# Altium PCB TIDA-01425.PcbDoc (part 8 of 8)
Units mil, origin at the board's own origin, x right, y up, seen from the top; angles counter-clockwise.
Board outline 7000 x 3600 mil, 6 copper layers (Layer 1 - Top Layer, Layer 2 - GND, Layer 3 - Signal / PWR, Layer 4 - Signal / PWR, Layer 5 - PWR, Layer 6 - Bottom Layer), stack 60.4 mil thick; 495 components, 307 nets, 2058 pads, 1870 vias.
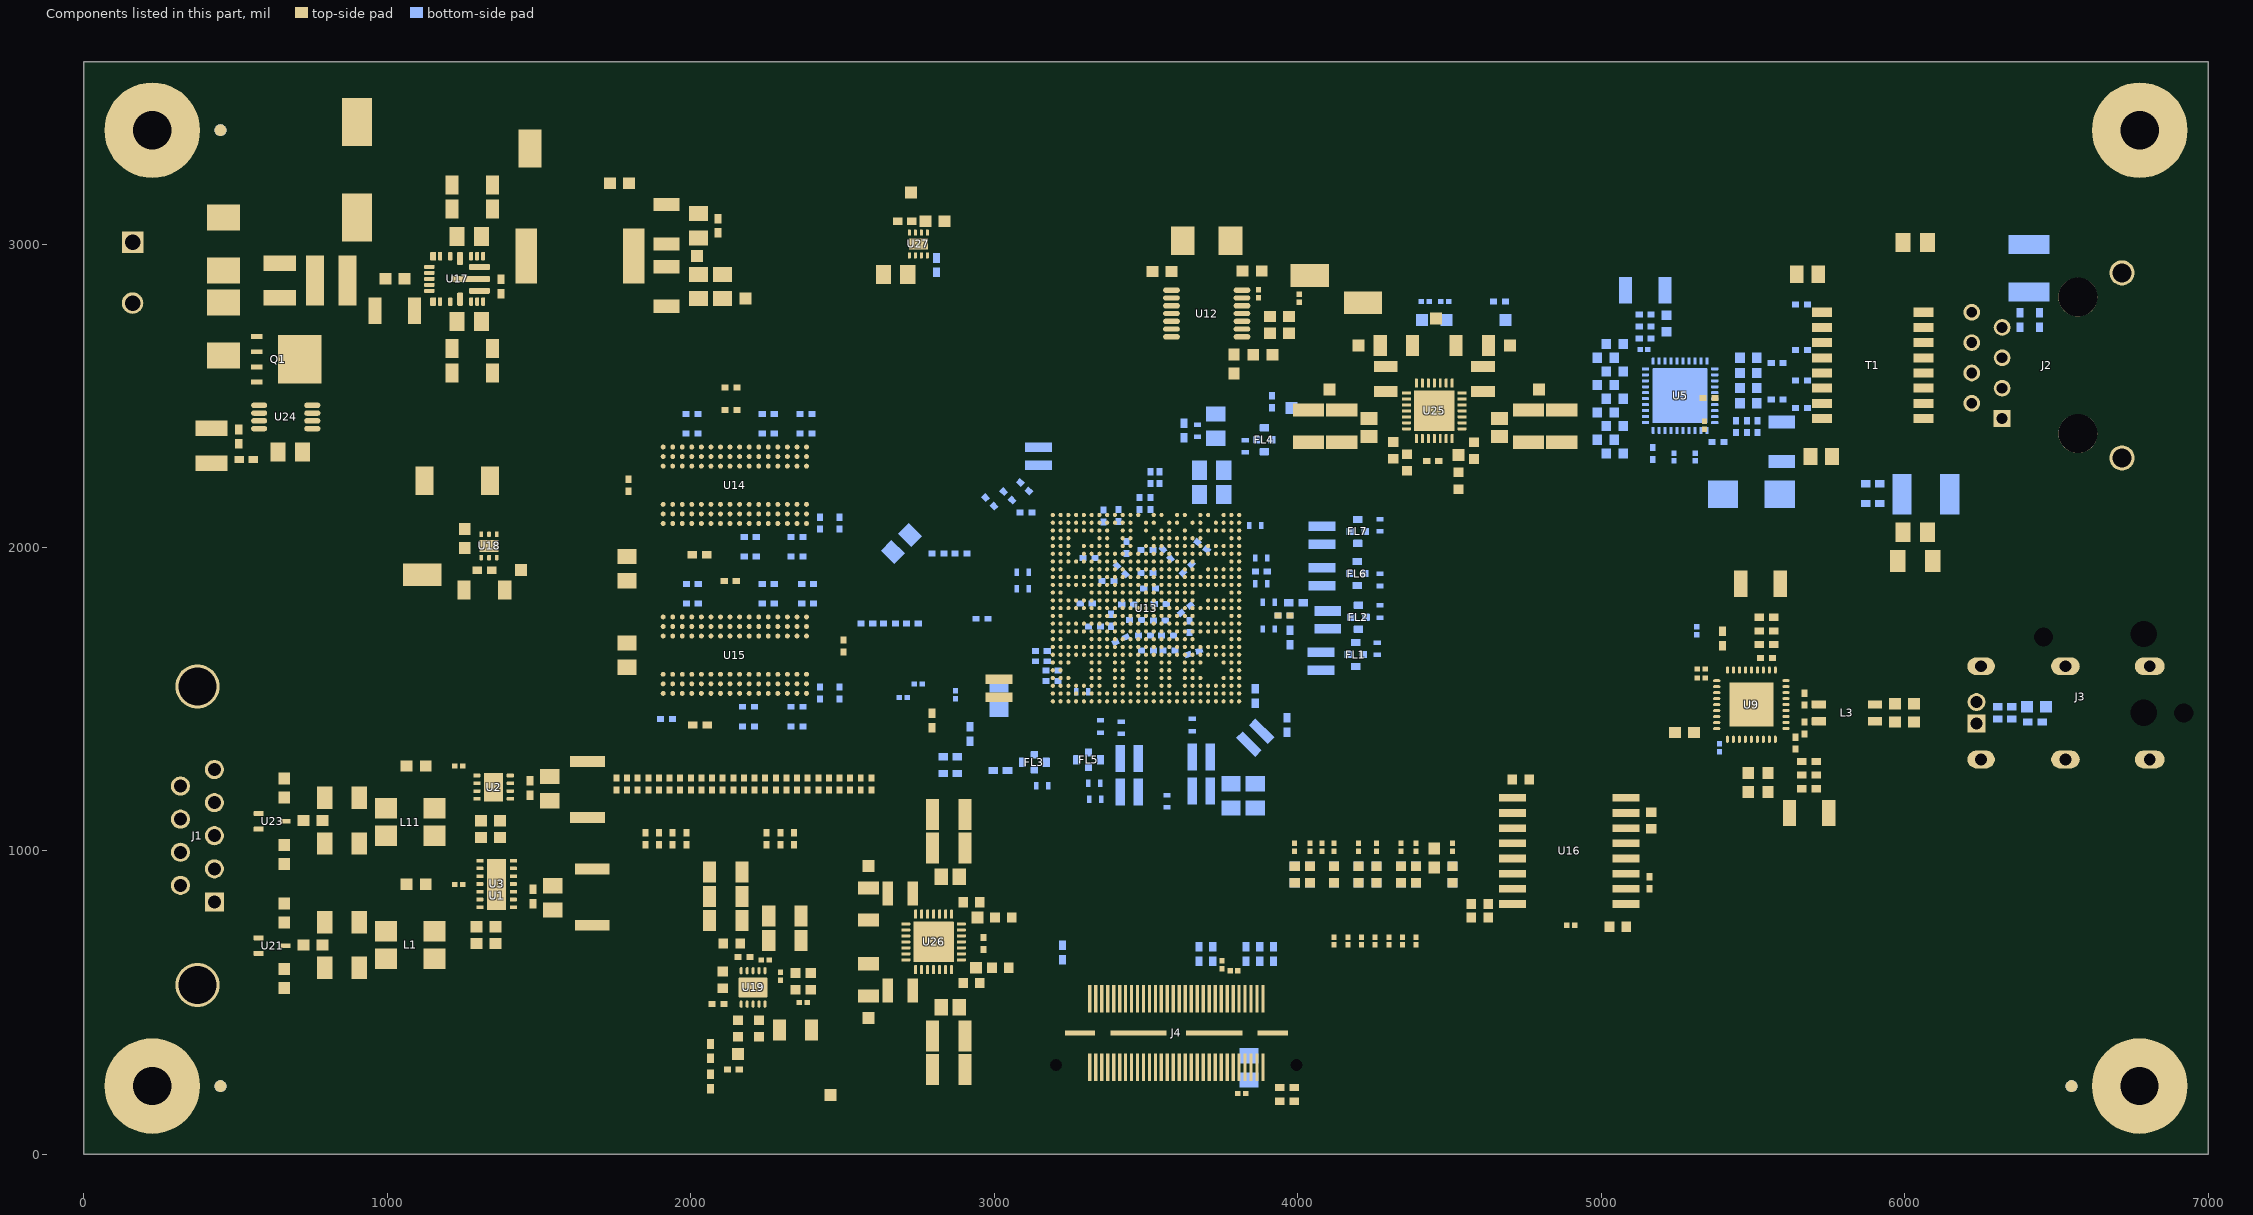
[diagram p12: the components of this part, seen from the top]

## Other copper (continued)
Layer 3 - Signal / PWR:
  pour cut-out: 6095,2325 5695,2325 5695,2875 6095,2875
  pour cut-out: 2655,1242.42 2655,1420 2986,1751 3258,1751 3332,1825 3332,2097 3500,2265 3500,2380 3260,2620 1884,2620 1771,2507 1771,1660 1697,1586 1697,1292 1697,1243.03
  pour cut-out: 3401.28,1813 3400.27,1818.08 3397.39,1822.38 3393.08,1825.26 3388,1826.27 3382.92,1825.26 3378.62,1822.38 3375.74,1818.08 3374.73,1813 3375.74,1807.92 3378.62,1803.61 3382.92,1800.73 3388,1799.72 3393.08,1800.73 3397.39,1803.61 3400.27,1807.92 3401.28,1813
  pour cut-out: 3446.28,1787.5 3445.27,1792.58 3442.39,1796.88 3438.08,1799.76 3433,1800.77 3427.92,1799.76 3423.62,1796.88 3420.74,1792.58 3419.73,1787.5 3420.74,1782.42 3423.62,1778.11 3427.92,1775.23 3433,1774.22 3438.08,1775.23 3442.39,1778.11 3445.27,1782.42 3446.28,1787.5
  pour cut-out: 3497.28,1787.5 3496.27,1792.58 3493.39,1796.88 3489.08,1799.76 3484,1800.77 3478.92,1799.76 3474.62,1796.88 3471.74,1792.58 3470.73,1787.5 3471.74,1782.42 3474.62,1778.11 3478.92,1775.23 3484,1774.22 3489.08,1775.23 3493.39,1778.11 3496.27,1782.42 3497.28,1787.5
  pour cut-out: 3497.53,1889.65 3496.52,1894.73 3493.64,1899.03 3489.33,1901.91 3484.25,1902.92 3479.17,1901.91 3474.87,1899.03 3471.99,1894.73 3470.98,1889.65 3471.99,1884.57 3474.87,1880.26 3479.17,1877.38 3484.25,1876.37 3489.33,1877.38 3493.64,1880.26 3496.52,1884.57 3497.53,1889.65
  pour cut-out: 3446.08,1889.6 3445.07,1894.68 3442.19,1898.98 3437.88,1901.86 3432.8,1902.87 3427.72,1901.86 3423.42,1898.98 3420.54,1894.68 3419.53,1889.6 3420.54,1884.52 3423.42,1880.21 3427.72,1877.33 3432.8,1876.32 3437.88,1877.33 3442.19,1880.21 3445.07,1884.52 3446.08,1889.6
  pour cut-out: 3471.38,1838.5 3470.37,1843.58 3467.49,1847.88 3463.18,1850.76 3458.1,1851.77 3453.02,1850.76 3448.72,1847.88 3445.84,1843.58 3444.83,1838.5 3445.84,1833.42 3448.72,1829.11 3453.02,1826.23 3458.1,1825.22 3463.18,1826.23 3467.49,1829.11 3470.37,1833.42 3471.38,1838.5
  pour cut-out: 3522.78,1838.5 3521.77,1843.58 3518.89,1847.88 3514.58,1850.76 3509.5,1851.77 3504.42,1850.76 3500.12,1847.88 3497.24,1843.58 3496.23,1838.5 3497.24,1833.42 3500.12,1829.11 3504.42,1826.23 3509.5,1825.22 3514.58,1826.23 3518.89,1829.11 3521.77,1833.42 3522.78,1838.5
  pour cut-out: 3548.68,1787 3547.67,1792.08 3544.79,1796.38 3540.48,1799.26 3535.4,1800.27 3530.32,1799.26 3526.02,1796.38 3523.14,1792.08 3522.13,1787 3523.14,1781.92 3526.02,1777.61 3530.32,1774.73 3535.4,1773.72 3540.48,1774.73 3544.79,1777.61 3547.67,1781.92 3548.68,1787
  pour cut-out: 3548.78,1889.4 3547.77,1894.48 3544.89,1898.78 3540.58,1901.66 3535.5,1902.67 3530.42,1901.66 3526.12,1898.78 3523.24,1894.48 3522.23,1889.4 3523.24,1884.32 3526.12,1880.01 3530.42,1877.13 3535.5,1876.12 3540.58,1877.13 3544.89,1880.01 3547.77,1884.32 3548.78,1889.4
  pour cut-out: 3573.78,1838.5 3572.77,1843.58 3569.89,1847.88 3565.58,1850.76 3560.5,1851.77 3555.42,1850.76 3551.12,1847.88 3548.24,1843.58 3547.23,1838.5 3548.24,1833.42 3551.12,1829.11 3555.42,1826.23 3560.5,1825.22 3565.58,1826.23 3569.89,1829.11 3572.77,1833.42 3573.78,1838.5
  pour cut-out: 2989.3,1463 2988.21,1468.47 2985.11,1473.1 2980.47,1476.2 2975,1477.29 2969.53,1476.2 2964.9,1473.1 2961.8,1468.47 2960.71,1463 2961.8,1457.53 2964.9,1452.89 2969.53,1449.79 2975,1448.7 2980.47,1449.79 2985.11,1452.89 2988.21,1457.53 2989.3,1463
  pour cut-out: 2936.3,1453.51 2935.21,1458.98 2932.11,1463.61 2927.47,1466.71 2922,1467.8 2916.53,1466.71 2911.9,1463.61 2908.8,1458.98 2907.71,1453.51 2908.8,1448.04 2911.9,1443.4 2916.53,1440.3 2922,1439.21 2927.47,1440.3 2932.11,1443.4 2935.21,1448.04 2936.3,1453.51
  pour cut-out: 3073.9,1463 3072.81,1468.47 3069.71,1473.1 3065.07,1476.2 3059.6,1477.29 3054.13,1476.2 3049.5,1473.1 3046.4,1468.47 3045.31,1463 3046.4,1457.53 3049.5,1452.89 3054.13,1449.79 3059.6,1448.7 3065.07,1449.79 3069.71,1452.89 3072.81,1457.53 3073.9,1463
  pour cut-out: 3206.87,1471.22 3205.86,1476.3 3202.98,1480.6 3198.67,1483.48 3193.59,1484.49 3188.51,1483.48 3184.21,1480.6 3181.33,1476.3 3180.32,1471.22 3181.33,1466.14 3184.21,1461.83 3188.51,1458.95 3193.59,1457.94 3198.67,1458.95 3202.98,1461.83 3205.86,1466.14 3206.87,1471.22
  pour cut-out: 3650.78,2017.5 3649.77,2022.58 3646.89,2026.88 3642.58,2029.76 3637.5,2030.77 3632.42,2029.76 3628.12,2026.88 3625.24,2022.58 3624.23,2017.5 3625.24,2012.42 3628.12,2008.11 3632.42,2005.23 3637.5,2004.22 3642.58,2005.23 3646.89,2008.11 3649.77,2012.42 3650.78,2017.5
  pour cut-out: 3116.34,1655.01 3115.25,1660.48 3112.15,1665.11 3107.51,1668.21 3102.04,1669.3 3096.57,1668.21 3091.94,1665.11 3088.84,1660.48 3087.75,1655.01 3088.84,1649.54 3091.94,1644.9 3096.57,1641.8 3102.04,1640.71 3107.51,1641.8 3112.15,1644.9 3115.25,1649.54 3116.34,1655.01
  pour cut-out: 3343.78,1787.1 3342.77,1792.18 3339.89,1796.48 3335.58,1799.36 3330.5,1800.37 3325.42,1799.36 3321.12,1796.48 3318.24,1792.18 3317.23,1787.1 3318.24,1782.02 3321.12,1777.71 3325.42,1774.83 3330.5,1773.82 3335.58,1774.83 3339.89,1777.71 3342.77,1782.02 3343.78,1787.1
  pour cut-out: 3446.38,1659.1 3445.37,1664.18 3442.49,1668.48 3438.18,1671.36 3433.1,1672.37 3428.02,1671.36 3423.72,1668.48 3420.84,1664.18 3419.83,1659.1 3420.84,1654.02 3423.72,1649.71 3428.02,1646.83 3433.1,1645.82 3438.18,1646.83 3442.49,1649.71 3445.37,1654.02 3446.38,1659.1
  pour cut-out: 3462.1,2124.04 3461.09,2129.12 3458.21,2133.42 3453.9,2136.3 3448.82,2137.31 3443.74,2136.3 3439.44,2133.42 3436.56,2129.12 3435.55,2124.04 3436.56,2118.96 3439.44,2114.65 3443.74,2111.77 3448.82,2110.76 3453.9,2111.77 3458.21,2114.65 3461.09,2118.96 3462.1,2124.04
  pour cut-out: 5695,2398.81 5671.19,2398.81 5655,2415 5655,2445 5650,2450 5630,2450 5607,2473 5595,2473 5588,2466 5500,2466 5482,2484 5392,2484 5301,2575 5301,2686 5368,2753 5648,2753 5654,2759 5654,2788 5665,2799 5695,2799
  text ".Layer_Name" at 577,-858.49 h60
Layer 4 - Signal / PWR:
  pour cut-out: 6095,2325 5695,2325 5695,2875 6095,2875
  pour cut-out: 3936.99,1913.21 3935.91,1918.68 3932.81,1923.32 3928.17,1926.42 3922.7,1927.5 3917.23,1926.42 3912.59,1923.32 3909.49,1918.68 3908.41,1913.21 3909.49,1907.74 3912.59,1903.1 3917.23,1900 3922.7,1898.92 3928.17,1900 3932.81,1903.1 3935.91,1907.74 3936.99,1913.21
  pour cut-out: 2655,1242.41 2655,1420 2986,1751 3258,1751 3346,1839 3346,1997 3456.24,2107.24 3456.24,2141.93 3500,2185.7 3500,2380 3260,2620 1884,2620 1771,2507 1771,1660 1697,1586 1697,1292 1697,1243.01
  pour cut-out: 4261.3,2053 4260.21,2058.47 4257.11,2063.1 4252.47,2066.2 4247,2067.29 4241.53,2066.2 4236.9,2063.1 4233.8,2058.47 4232.71,2053 4233.8,2047.53 4236.9,2042.89 4241.53,2039.79 4247,2038.7 4252.47,2039.79 4257.11,2042.89 4260.21,2047.53 4261.3,2053
  pour cut-out: 4154.3,2053 4153.21,2058.47 4150.11,2063.1 4145.47,2066.2 4140,2067.29 4134.53,2066.2 4129.9,2063.1 4126.8,2058.47 4125.71,2053 4126.8,2047.53 4129.9,2042.89 4134.53,2039.79 4140,2038.7 4145.47,2039.79 4150.11,2042.89 4153.21,2047.53 4154.3,2053
  pour cut-out: 4151.4,2018.1 4150.31,2023.57 4147.21,2028.2 4142.57,2031.3 4137.1,2032.39 4131.63,2031.3 4127,2028.2 4123.9,2023.57 4122.81,2018.1 4123.9,2012.63 4127,2007.99 4131.63,2004.89 4137.1,2003.8 4142.57,2004.89 4147.21,2007.99 4150.31,2012.63 4151.4,2018.1
  pour cut-out: 4079.3,2380 4078.21,2385.47 4075.11,2390.1 4070.47,2393.2 4065,2394.29 4059.53,2393.2 4054.9,2390.1 4051.8,2385.47 4050.71,2380 4051.8,2374.53 4054.9,2369.89 4059.53,2366.79 4065,2365.7 4070.47,2366.79 4075.11,2369.89 4078.21,2374.53 4079.3,2380
  pour cut-out: 4050.8,2053.1 4049.71,2058.57 4046.61,2063.2 4041.97,2066.3 4036.5,2067.39 4031.03,2066.3 4026.4,2063.2 4023.3,2058.57 4022.21,2053.1 4023.3,2047.63 4026.4,2042.99 4031.03,2039.89 4036.5,2038.8 4041.97,2039.89 4046.61,2042.99 4049.71,2047.63 4050.8,2053.1
  pour cut-out: 4050.9,2018.1 4049.81,2023.57 4046.71,2028.2 4042.07,2031.3 4036.6,2032.39 4031.13,2031.3 4026.5,2028.2 4023.4,2023.57 4022.31,2018.1 4023.4,2012.63 4026.5,2007.99 4031.13,2004.89 4036.6,2003.8 4042.07,2004.89 4046.71,2007.99 4049.81,2012.63 4050.9,2018.1
  pour cut-out: 3972.3,2355 3971.21,2360.47 3968.11,2365.1 3963.47,2368.2 3958,2369.29 3952.53,2368.2 3947.9,2365.1 3944.8,2360.47 3943.71,2355 3944.8,2349.53 3947.9,2344.89 3952.53,2341.79 3958,2340.7 3963.47,2341.79 3968.11,2344.89 3971.21,2349.53 3972.3,2355
  pour cut-out: 3943.3,1390 3942.21,1395.47 3939.11,1400.1 3934.47,1403.2 3929,1404.29 3923.53,1403.2 3918.9,1400.1 3915.8,1395.47 3914.71,1390 3915.8,1384.53 3918.9,1379.89 3923.53,1376.79 3929,1375.7 3934.47,1376.79 3939.11,1379.89 3942.21,1384.53 3943.3,1390
  pour cut-out: 3918.6,2072.8 3917.51,2078.27 3914.41,2082.9 3909.77,2086 3904.3,2087.09 3898.83,2086 3894.2,2082.9 3891.1,2078.27 3890.01,2072.8 3891.1,2067.33 3894.2,2062.69 3898.83,2059.59 3904.3,2058.5 3909.77,2059.59 3914.41,2062.69 3917.51,2067.33 3918.6,2072.8
  pour cut-out: 3850.5,1430.2 3849.41,1435.67 3846.31,1440.3 3841.67,1443.4 3836.2,1444.49 3830.73,1443.4 3826.1,1440.3 3823,1435.67 3821.91,1430.2 3823,1424.73 3826.1,1420.09 3830.73,1416.99 3836.2,1415.9 3841.67,1416.99 3846.31,1420.09 3849.41,1424.73 3850.5,1430.2
  pour cut-out: 3876.2,1455.3 3875.11,1460.77 3872.01,1465.4 3867.37,1468.5 3861.9,1469.59 3856.43,1468.5 3851.8,1465.4 3848.7,1460.77 3847.61,1455.3 3848.7,1449.83 3851.8,1445.19 3856.43,1442.09 3861.9,1441 3867.37,1442.09 3872.01,1445.19 3875.11,1449.83 3876.2,1455.3
  pour cut-out: 3835.98,1477.3 3834.97,1482.38 3832.09,1486.68 3827.78,1489.56 3822.7,1490.57 3817.62,1489.56 3813.32,1486.68 3810.44,1482.38 3809.43,1477.3 3810.44,1472.22 3813.32,1467.91 3817.62,1465.03 3822.7,1464.02 3827.78,1465.03 3832.09,1467.91 3834.97,1472.22 3835.98,1477.3
  pour cut-out: 3630.78,1659.3 3629.77,1664.38 3626.89,1668.68 3622.58,1671.56 3617.5,1672.57 3612.42,1671.56 3608.12,1668.68 3605.24,1664.38 3604.23,1659.3 3605.24,1654.22 3608.12,1649.91 3612.42,1647.03 3617.5,1646.02 3622.58,1647.03 3626.89,1649.91 3629.77,1654.22 3630.78,1659.3
  pour cut-out: 3666.3,1365 3665.21,1370.47 3662.11,1375.1 3657.47,1378.2 3652,1379.29 3646.53,1378.2 3641.9,1375.1 3638.8,1370.47 3637.71,1365 3638.8,1359.53 3641.9,1354.89 3646.53,1351.79 3652,1350.7 3657.47,1351.79 3662.11,1354.89 3665.21,1359.53 3666.3,1365
  pour cut-out: 3600.13,1684.65 3599.12,1689.73 3596.24,1694.03 3591.93,1696.91 3586.85,1697.92 3581.77,1696.91 3577.47,1694.03 3574.59,1689.73 3573.58,1684.65 3574.59,1679.57 3577.47,1675.26 3581.77,1672.38 3586.85,1671.37 3591.93,1672.38 3596.24,1675.26 3599.12,1679.57 3600.13,1684.65
  pour cut-out: 3548.08,1684.8 3547.07,1689.88 3544.19,1694.18 3539.88,1697.06 3534.8,1698.07 3529.72,1697.06 3525.42,1694.18 3522.54,1689.88 3521.53,1684.8 3522.54,1679.72 3525.42,1675.41 3529.72,1672.53 3534.8,1671.52 3539.88,1672.53 3544.19,1675.41 3547.07,1679.72 3548.08,1684.8
  pour cut-out: 3581.5,1363.3 3580.41,1368.77 3577.31,1373.4 3572.67,1376.5 3567.2,1377.59 3561.73,1376.5 3557.1,1373.4 3554,1368.77 3552.91,1363.3 3554,1357.83 3557.1,1353.19 3561.73,1350.09 3567.2,1349 3572.67,1350.09 3577.31,1353.19 3580.41,1357.83 3581.5,1363.3
  text ".Layer_Name" at 577,-858.49 h60
Layer 5 - PWR:
  pour cut-out: 6095,2325 5695,2325 5695,2875 6095,2875
  pour cut-out: 4400,2335 ccw(c4400,2315.67) 4380.67,2315.67 4380.67,2313.94 ccw(c4400,2313.94) 4400,2294.61 ccw(c4400,2314.61) 4420,2314.61 4420,2315 ccw(c4400,2315)
  pour cut-out: 4430.31,2350 ccw(c4430.31,2330.67) 4410.98,2330.67 4410.98,2328.94 ccw(c4430.31,2328.94) 4430.31,2309.61 ccw(c4430.31,2329.61) 4450.31,2329.61 4450.31,2330 ccw(c4430.31,2330)
  text ".Layer_Name" at 577,-858.49 h60
Layer 6 - Bottom Layer:
  pour cut-out: 5135,2375 5385,2375 5385,2625 5135,2625
  pour cut-out: 6095,2325 5695,2325 5695,2875 6095,2875
  region net GND: 3504,2237 3556,2237 3556,2285 3504,2285
  region net GND: 3730,2290 3795,2290 3806,2279 3806,2167 3781,2142 3730,2142
  region net SW_3V3: 3564.34,2225 3629.34,2290 3705,2290 3705,2142 3562,2142 3555,2149 3437,2149 3437,2179 3483,2225
  region net VDDS_1V8: 3659,1638 3655,1634 3655,1530 3694,1491 3789,1491 3815,1517 3886,1517 3922,1481 3922,1442 3941,1423 3988,1423 4009,1402 4300,1402 4314,1416 4314,1463 4301,1476 4066,1476 3966,1576 3797,1576 3758,1537 3726,1537 3713,1550 3713,1585 3687,1611 3687,1630 3679,1638
  region net GND: 3665,1405 3670,1400 3670,1140 3660,1130 3645,1130 3635,1140 3635,1405
  region net GND: 3875,1505 3905,1475 3905,1440 3935,1410 3975,1410 3985,1400 3985,1350 3975,1340 3905,1340 3810,1435 3810,1490 3825,1505
  region net GND: 3745,1110 3903.65,1110 3913.19,1119.54 3913.19,1156.81 3900,1170 3750,1170 3745,1165
  region net GND: 3070,1493 3070,1458 3053,1441 2979,1441 2964,1456 2964,1493
  region net GND: 2707,1980 2707,1964 2670,1927 2659,1927 2611,1975 2611,1991 2645,2025 2662,2025
  region net VDD_DDR_1V35: 2726,2000 2756,2000 2769,2013 2769,2045 2718,2096 2706,2096 2682,2072 2682,2044
  region net GND: 5435,2393 5525,2393 5580,2338 5645,2338 5645,2113 5530,2113 5530,2278 5465,2343 5430,2343 5430,2388
  region net SW_3V3: 5430,2408 5435,2403 5535,2403 5580,2358 5645,2358 5645,2438 5430,2438
  region net SW_3V3: 5495,2643 5495,2453 5570,2453 5575,2458 5575,2638 5570,2643
  region net GND: 20,20 6980,20 6980,2060 6980,3130 6980,3580 20,3580 20,40 40,40 40,3560 6960,3560 6960,3150 6960,2040 6960,40 20,40
  region net NetR15_2: 5177,2602 5158,2602 5144,2616 5144,2662 5168,2662 5177,2653
  region net SW_3V3: 5138,2644 5138,2881 5127,2892 5057,2892 5057,2798 5105,2750 5105,2656 5117,2644
  region net GND: 5152,2677 5152,2881 5163,2892 5232,2892 5232,2804 5227,2799 5188,2799 5177,2788 5177,2677
  region net SW_3V3: 4423,2801 4482,2801 4482,2833 4475,2840 4430,2840 4423,2833
  pour cut-out: 2637,1220.86 2637,1432 3072.5,1867.5 3314,1867.5 3349,1832.5 3349,1654.1 3492.15,1654.1 3511,1672.94 3511,1797.1 3556,1842.1 3556,1942.03 3555,1965 3540,1980 3465,1980 3435,2010 3435,2085 3435,2109.61 3349.61,2109.61 3344.22,2115 3344.22,2289.22 3375,2320 3375,2520 3275,2620 1884,2620 1771,2507 1771,1660 1697,1586 1697,1221.46
  pour cut-out: 1837.3,2182 1836.21,2187.47 1833.11,2192.1 1828.47,2195.2 1823,2196.29 1817.53,2195.2 1812.9,2192.1 1809.8,2187.47 1808.71,2182 1809.8,2176.53 1812.9,2171.89 1817.53,2168.79 1823,2167.7 1828.47,2168.79 1833.11,2171.89 1836.21,2176.53 1837.3,2182
  region net SYS_3V3: 2845,1140 2845,991.01 2833.7,979.71 2760.29,979.71 2750,990 2750,1140 2760,1150 2835,1150
  text ".Layer_Name" at 577,-858.49 h60

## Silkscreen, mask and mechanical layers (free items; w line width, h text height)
Top Overlay:
  circle w10: c525,833 r5
  circle w10: c5660,2775 r5
  circle w10: c4365,2365 r5
  circle w10: c3530,2850 r5
  circle w10: c2685,2960 r5
  circle w10: c1150,2775 r5
  circle w10: c575,2515 r5
  circle w10: c1240,1945 r5
  circle w10: c1440,1135 r5
  circle w10: c1415,770 r5
  circle w10: c2290,630 r5
  circle w10: c2935,665 r5
  circle w10: c5415,1335 r5
  circle w10: c3930,575 r5
  text "SW 3V3" at 2765,3155 h50
  text "TX EN" at 5295,2805 h50 r90
  text "TX D1" at 5345,2805 h50 r90
  text "TX D3" at 5395,2805 h50 r90
  text "GND" at 4405,2785 h50
  text "RX D3" at 5009,2655 h50
  text "VDD CORE" at 3930,2635 h50
  text "VDD DSP" at 4735,2635 h50
  text "RX D2" at 4979,2610 h50
  text "TX CLK" at 5270,2585 h50 r90
  text "TX D0" at 5320,2585 h50 r90
  text "TX D2" at 5370,2585 h50 r90
  text "RX D1" at 5009,2565 h50
  text "RX D0" at 4979,2520 h50
  text "SYS 3V3" at 3890,2505 h50
  text "COL" at 5009,2475 h50
  text "RX ER" at 4979,2430 h50
  text "CRS" at 5009,2385 h50
  text "RX DV" at 4974,2340 h50
  text "RX CLK" at 5009,2295 h50
  text "AE25" at 3165,2155 h50
  text "RX CLK" at 5210,1695 h50 r90
  text "RX D0" at 5290,1695 h50 r90
  text "RX D1" at 5330,1695 h50 r90
  text "RX D2" at 5370,1695 h50 r90
  text "RX D3" at 5480,1695 h50 r90
  text "RX CTRL" at 5660,1645 h50 r90
  text "TX CLK" at 5015,1620 h50
  text "TX CTRL" at 4985,1580 h50
  text "TX D3" at 5050,1540 h50
  text "TX D2" at 5050,1500 h50
  text "TX D1" at 5050,1460 h50
  text "TX D0" at 5050,1420 h50
  text "A1" at 3845,1410 h50
  text "DDR 1V35" at 2490,985 h50
  text "VDDS 1V8" at 2480,335 h50
  text "GND" at 2415,125 h50
  text ".Layer_Name" at 577,-858.49 h60
Bottom Overlay:
  circle w10: c5110,2630 r5
  text "SDA" at 4370,2715 h50
  text "SCL" at 4610,2715 h50
  text "H PORZ" at 4880,2715 h50
  text ".Layer_Name" at 577,-858.49 h60
Top Paste:
  text ".Layer_Name" at 577,-858.49 h60
Bottom Paste:
  text ".Layer_Name" at 577,-858.49 h60
Top Solder:
  region: 20,20 6980,20 6980,2240 6980,2960 6980,3580 20,3580 20,40 40,40 40,3560 6960,3560 6960,2980 6960,2220 6960,40 20,40
  text ".Layer_Name" at 577,-858.49 h60
  text ".Layer_Name" at 577,-858.49 h60
Bottom Solder:
  region: 20,20 6980,20 6980,2060 6980,3130 6980,3580 20,3580 20,40 40,40 40,3560 6960,3560 6960,3150 6960,2040 6960,40 20,40
  text ".Layer_Name" at 577,-858.49 h60
Drill Guide:
  text ".Layer_Name" at 577,-858.49 h60
M1 Board Outline:
  the board outline again, w10
  text ".Layer_Name" at 577,-858.49 h60
M2 Board Dimensions:
  rectangle: 125,-400 500,-275
  rectangle: 0,-275 125,-150
  lines w7: 0,-275 1000,-275 ; 125,-400 125,-150 ; 250,-400 250,-150 ; 500,-400 500,-150 ; 750,-400 750,-150 ; 0,-400 0,-150 1000,-150 1000,-400 0,-400
  text ".Layer_Name" at 577,-858.49 h60
M3 3D STEP Top:
  text ".Layer_Name" at 577,-858.49 h60
M4 3D STEP Bottom:
  text ".Layer_Name" at 577,-858.49 h60
M5 Assembly Top:
  lines w10: -292,-930.17 6308,-930.17 ; -292,-726.83 6310,-726.83 ; -292,-523.5 -292,-1133.5 3713,-1133.5 6310,-1133.5 6310,-523.5 -291.5,-523.5 -291.5,-1133.5 1284,-1133.5 ; 2173,-1133.5 2173,-523.5 ; 3440,-726.83 3440,-523.5 ; 4280,-726.83 4280,-523.5 ; 4902,-1140 4902,-937.17
  text "COMPONENTS MARKED 'DNP' SHOULD NOT BE POPULATED." at 1153.5,-318.5 h60
  text "ASSEMBLY VARIANT:" at 1153,-434 h60
  text ".VariantName" at 2189,-434 h60
  text "PCB VIEWED FROM TOP SIDE" at -228.5,-655.67 h60
  text "BOARD #:" at 2248,-655.67 h60
  text ".PRJ_Number" at 2793.5,-655.67 h60
  text "REV:" at 3638,-655.67 h60
  text ".PCB_Rev" at 3929.5,-655.67 h60
  text "SVN REV:" at 4476,-655.67 h60
  text ".VersionControl_RevNumber" at 4982,-655.67 h60
  text "TID #:" at 2248,-859 h60
  text ".TID" at 2793.5,-859 h60
  text "PLOT NAME =" at -228.5,-1064.34 h60
  text ".plot_File_Name" at 577,-1064.34 h60
  text "GENERATED    :" at 2250,-1064.34 h60
  text ".Print_Date" at 3119.5,-1064.34 h60
  text ".Print_Time" at 3848.5,-1064.34 h60
  text "TEXAS INSTRUMENTS" at 5113,-1064.34 h60
M6 Assembly Bottom:
  lines w10: -292.5,-727.33 6309.5,-727.33 ; -290.5,-930.67 6309.5,-930.67 ; 1115.5,-1140.5 1115.5,-937.67 ; 1737.5,-727.33 1737.5,-524 ; 2577.5,-727.33 2577.5,-524 ; 3844.5,-1134 3844.5,-524 ; 4733.5,-1134 6309,-1134 6309,-524 -292.5,-524 -292.5,-1134 2304.5,-1134 6309.5,-1134 6309.5,-524
  text "COMPONENTS MARKED 'DNP' SHOULD NOT BE POPULATED." at 6102,-318 h60
  text ".VariantName" at 5058,-434 h60
  text "ASSEMBLY VARIANT:" at 6097,-434 h60
  text ".VersionControl_RevNumber" at 1035.5,-656.17 h60
  text "SVN REV:" at 1541.5,-656.17 h60
  text ".PCB_Rev" at 2088,-656.17 h60
  text "REV:" at 2379.5,-656.17 h60
  text ".PRJ_Number" at 3224,-656.17 h60
  text "BOARD #:" at 3769.5,-656.17 h60
  text "PCB VIEWED FROM BOTTOM SIDE" at 6246,-656.17 h60
  text ".TID" at 3224,-859.5 h60
  text "TID #:" at 3769.5,-859.5 h60
  text "TEXAS INSTRUMENTS" at 904.5,-1064.84 h60
  text ".Print_Time" at 2169,-1064.84 h60
  text ".Print_Date" at 2898,-1064.84 h60
  text "GENERATED    :" at 3767.5,-1064.84 h60
  text ".plot_File_Name" at 5440.5,-1064.84 h60
  text "PLOT NAME =" at 6246,-1064.84 h60
M9 Title Sheet:
  drawing of 1178 lines, arcs and shapes, not listed
  text "1" at 739.84,8036.5 h70
  text "2" at 3235.5,8036.5 h70
  text "3" at 5724.84,8036.5 h70
  text "4" at 8231.51,8036.5 h70
  text "5" at 10730.5,8036.5 h70
  text "6" at 13235.5,8036.5 h70
  text "A" at -416.5,6893.5 h70
  text "A" at 14383.5,6893.5 h70
  text "B" at -416.5,4513.5 h70
  text "B" at 14383.5,4513.5 h70
  text "C" at -416.5,2138.5 h70
  text "C" at 14383.5,2138.5 h70
  text "PROJECT TITLE:" at 11343.5,277.5 h45
  text ".PRJ_Title" at 11393.5,144.17 h70
  text "DESIGNED FOR:" at 11343.5,-23.5 h45
  text ".PRJ_Customer" at 11393.5,-163.5 h70
  text "D" at -416.5,-231.5 h70
  text "D" at 14383.5,-231.5 h70
  text "FILE NAME:" at 11343.5,-323.5 h45
  text ".PCB_File_Name_No_Path" at 11393.5,-443.5 h70
  text "Texas Instruments (TI) and/or its licensors do not warrant the accuracy or completeness of this specification" at 6374,-605.34 h45
  text "ENGINEER:" at 11343.5,-613.5 h45
  text "LAYOUT BY:" at 12848.5,-613.5 h45
  text ".PRJ_Engineer" at 11680,-630 h70
  text "or any information contained therein. TI and/or its licensors do not warrant that this design will meet" at 6329.01,-718 h45
  text ".PRJ_Engineer2" at 11680,-750 h70
  text "JMM" at 12852,-800 h100
  text "s  o  l  u  t  i  o  n  s" at 13710,-803 h68
  text "the specifications, will be suitable for your application or fit for any particular purpose, or will operate in" at 6329.01,-830.67 h45
  text ".Layer_Name" at 577,-858.49 h60
  text "ALTIUM DESIGNER VERSION:" at 12848.5,-923.5 h45
  text "an implementation. TI and/or its licensors do not warrant that the design is production worthy. You should" at 6329.01,-943.33 h45
  text "completely validate and test your design implementation to confirm the system functionality for your application." at 6374,-1056 h45
  text ".print_Scale" at 11393.5,-1056.83 h70
  text ".Application_BuildNumber" at 12899,-1056.83 h70
  text "1" at 739.84,-1263.5 h70
  text "2" at 3235.5,-1263.5 h70
  text "3" at 5724.84,-1263.5 h70
  text "4" at 8231.51,-1263.5 h70
  text "5" at 10730.5,-1263.5 h70
  text "6" at 13235.5,-1263.5 h70
M10 Fab Notes:
  drawing of 175 lines, arcs and shapes, not listed
  text "DESIGN INFORMATION" at 12378.02,6201 h60
  text "MIN. TRACK WIDTH:" at 11733.46,6021 h60
  text "MIL" at 12984.46,6021 h60
  text "4" at 12820,6020 h60
  text "MIN. CLEARANCE:" at 11733.46,5889 h60
  text "0.2" at 12769.7,5889 h60
  text "mm" at 12984.46,5889 h60
  text "MIN. VIA PAD SIZE:" at 11733.46,5757 h60
  text "18" at 12799.71,5757 h60
  text "MIL" at 12984.46,5757 h60
  text "0.05mm (2MIL)" at 12428.46,5615.29 h60
  text "MINIMUM ANNULAR RING" at 11404.23,5611 h60
  text "EXTERNAL" at 13136.46,5611 h60
  text "PER" at 11604.23,5493 h60
  text "IPC-D-275 CLASS 2 LEVEL C" at 11824.23,5493 h60
  text "Impedance Control:" at 7279,5438 h200
  text "MIL, HOLES" at 13312.46,5380.71 h60
  text "+/-" at 12920,5380 h60
  text "+/-" at 13774,5380 h60
  text "REGISTRATION TOLERANCES:" at 11404.23,5375 h60
  text "METAL" at 12604,5375 h60
  text "5" at 13180.2,5375 h60
  text "3" at 14013.2,5375 h60
  text "MIL" at 14129.46,5375 h60
  text "+/-" at 13774,5262 h60
  text "HOLE SIZE TOLERANCE (UNLESS OTHERWISE SPECIFIED):" at 11404.23,5257 h60
  text "3" at 14013.2,5257 h60
  text "MIL" at 14129.46,5257 h60
  text "Top Layer: 50 ohm impedance (+/- 10%) single ended for 5 mil traces." at 7278,5136 h125
  text "MATERIAL:" at 11329.46,5047.54 h60
  text "Top Layer: 100 ohm impedance (+/-10%) for diff. pairs with" at 7278,4950 h125
  text "FR-4 High Tg" at 12315.9,4907.21 h60
  text "FR-408" at 11750.46,4898.64 h60
  text "OTHER" at 13238.46,4898.64 h60
  text "X" at 12161,4895 h60
  text "4.4 mil width and 9.6 mil spacing." at 7907,4799 h125
  text "62 MIL (1.6mm) +/-10%" at 12070.56,4735.92 h60
  text "THICKNESS:" at 11404.23,4731.64 h60
  text "X" at 11942.4,4731.64 h60
  text "OTHER" at 13355.46,4731.64 h60
  text "Layer 3: 50 ohm impedance (+/- 10%) single ended for 5.25 mil traces." at 7280,4635 h125
  text "TOLERANCE:" at 11404.23,4573.64 h60
  text "X" at 12243.53,4573.64 h60
  text "ANSI IPC-6012 TYPE 3 CLASS 2" at 12430.48,4573.64 h60
  text "Layer 3: 100 ohm impedance (+/-10%) for diff. pairs with" at 7280,4435 h125
  text "OTHER +/-" at 12430.46,4417.64 h60
  text "4.5 mil width and 9.6 mil spacing." at 7909,4284 h125
  text "BOW & TWIST:" at 11404.23,4260.64 h60
  text "X" at 12243.53,4260.64 h60
  text "ANSI IPC-6012 TYPE 3 CLASS 2" at 12430.48,4260.64 h60
  text "Layer 4: 50 ohm impedance (+/- 10%) single ended for 5.25 mil traces." at 7278,4118 h125
  text "OTHER +/-" at 12430.46,4102.13 h60
  text "DRILLING:" at 11329.46,3963.64 h60
  text "Bottom Layer: 50 ohm impedance (+/- 10%) single ended for 5 mil traces." at 7281,3900 h125
  text "REFERENCE:" at 11404.23,3846.64 h60
  text "X" at 12052.46,3846.64 h60
  text "AS SHOWN" at 12239.46,3846.64 h60
  text "X" at 12953.46,3846.64 h60
  text "NC_DRILL FILES" at 13090.46,3846.64 h60
  text "PTH COPPER THICKNESS:" at 11404.23,3688.64 h60
  text "X" at 12534.46,3688.64 h60
  text "20-30 um" at 12671.46,3688.64 h60
  text "OTHER" at 13388.46,3688.64 h60
  text "Fabrication Notes:" at 7286,3532 h200
  text "BOARD FINISH:" at 11329.46,3529.64 h60
  text "SILKSCREEN:" at 11484.68,3411.64 h60
  text "X" at 12433.46,3411.64 h60
  text "TOP" at 12559.46,3411.64 h60
  text "X" at 12943.46,3411.64 h60
  text "BOTTOM" at 13070.46,3411.64 h60
  text "Fab shop must delete all unused inner layer via pads." at 7280,3285 h125
  text "SILKSCREEN COLOR:" at 11484.68,3244.64 h60
  text "X" at 12432.42,3244.64 h60
  text "WHITE" at 12559.46,3244.64 h60
  text "OTHER" at 13070.46,3244.64 h60
  text "X" at 12563.42,3085.44 h60
  text "GREEN" at 12690.46,3085.44 h60
  text "OTHER" at 13308.46,3085.44 h60
  text "SOLDER RESIST COLOR:" at 11484.68,3074.64 h60
  text "X" at 12563.42,2915.44 h60
  text "MATTE" at 12690.46,2915.44 h60
  text "SEMI-GLOSS" at 13308,2914.8 h60
  text "IMMERSION GOLD (ENIG)" at 12390.46,2726.92 h60
  text "ENEPIG" at 13728,2723.64 h60
  text "SURFACE FINISH:" at 11329.46,2722.64 h60
  text "X" at 12203.51,2722.64 h60
  text "IMM. TIN/SILVER OR EQUIV" at 11659,2565.64 h60
  text "OTHER" at 13090.46,2565.64 h60
  text "ARRAY/PANEL:" at 11329.46,2386.64 h60
  text "CUT AND TRIM PER M1 BOARD OUTLINE" at 12390.46,2382.35 h60
  text "N.C. ROUTE" at 12390.46,2230.64 h60
  text "X" at 13069.46,2230.64 h60
  text "V. SCORE" at 13256.46,2230.64 h60
  text "CERTIFICATION:" at 11329.46,2093.64 h60
  text "MATERIALS AND WORKMANSHIP FOR ALL PCBS" at 12054.46,2093.64 h60
  text "TO MEET OR EXCEED THE REQUIREMENTS OF:" at 12054.46,1995.64 h60
  text "X" at 11680.96,1859.13 h60
  text "ANSI IPC-A-600F CLASS ->" at 11819.96,1859.13 h60
  text "X" at 13459.02,1859.13 h60
  text "2" at 13577.96,1859.14 h60
  text "1" at 13262.96,1857.64 h60
  text "3" at 13931.96,1857.64 h60
  text "X" at 12495.02,1699.64 h60
  text "RoHS" at 12631.96,1699.64 h60
  text "OTHER" at 13276.36,1699.64 h60
  text "PER ORDER" at 13673.42,1699.64 h60
  text "ALL BOARDS MUST MEET OR EXCEED UL94-V0 REQUIREMENTS." at 11357,1534 h60
  text "PCB MUST BEAR THE UL94V-0 UL REGISTERED MATERIAL ID NUMBER" at 11357,1414 h60
  text "ADDITIONAL REQUIREMENTS:" at 11329.46,1240.64 h60
  text "MICROSECTION:" at 11404.23,1125.64 h60
  text "YES" at 12309.96,1125.64 h60
  text "REQUIRED" at 13171.46,969.49 h60
  text "BARE BOARD ELEC. TEST:" at 11404.23,966.64 h60
  text "NONE" at 12709.96,966.64 h60
  text "X" at 13044.46,966.64 h60
  text "PER ORDER" at 13763.46,966.64 h60
  text ".Layer_Name" at 577,-858.49 h60
M11 Gerber Information:
  lines w10: -292,-930.17 6308,-930.17 ; -292,-726.83 6310,-726.83 ; -292,-523.5 -292,-1133.5 3713,-1133.5 6310,-1133.5 6310,-523.5 -291.5,-523.5 -291.5,-1133.5 1284,-1133.5 ; 2173,-1133.5 2173,-523.5 ; 3440,-726.83 3440,-523.5 ; 4280,-726.83 4280,-523.5 ; 4902,-1140 4902,-937.17
  text "ALL ARTWORK VIEWED FROM TOP SIDE" at -228.5,-655.67 h60
  text "BOARD #:" at 2248,-655.67 h60
  text ".PRJ_Number" at 2793.5,-655.67 h60
  text "REV:" at 3638,-655.67 h60
  text ".PCB_Rev" at 3929.5,-655.67 h60
  text "SVN REV:" at 4476,-655.67 h60
  text ".VersionControl_RevNumber" at 4982,-655.67 h60
  text "LAYER NAME =" at -228.5,-858.49 h60
  text "TID #:" at 2248,-859 h60
  text ".TID" at 2793.5,-859 h60
  text "PLOT NAME =" at -228.5,-1064.34 h60
  text ".plot_File_Name" at 577,-1064.34 h60
  text "GENERATED    :" at 2250,-1064.34 h60
  text ".Print_Date" at 3119.5,-1064.34 h60
  text ".Print_Time" at 3848.5,-1064.34 h60
  text "TEXAS INSTRUMENTS" at 5113,-1064.34 h60
M12 Stackup:
  drawing of 451 lines, arcs and shapes, not listed
  text "Layer" at 6182.5,7817.5 h60
  text "Name" at 6592.41,7817.5 h60
  text "Material" at 8012,7817.5 h60
  text "Thickness" at 8931.75,7817.5 h60
  text "Constant" at 9581.58,7817.5 h60
  text "Board Layer Stack" at 10151.44,7817.5 h60
  text "1" at 6182.5,7697.5 h60
  text "Top Overlay" at 6592.41,7697.5 h60
  text "2" at 6182.5,7577.5 h60
  text "Top Solder" at 6592.41,7577.5 h60
  text "Solder Resist" at 8012,7577.5 h60
  text "0.50mil" at 8931.75,7577.5 h60
  text "3.5" at 9581.58,7577.5 h60
  text "3" at 6182.5,7457.5 h60
  text "Layer 1 - Top Layer" at 6592.41,7457.5 h60
  text "Copper" at 8012,7457.5 h60
  text "1.20mil" at 8931.75,7457.5 h60
  text "4" at 6182.5,7337.5 h60
  text "Dielectric 1" at 6592.41,7337.5 h60
  text "370H (1080HRC)" at 8012,7337.5 h60
  text "3.40mil" at 8931.75,7337.5 h60
  text "4.2" at 9581.58,7337.5 h60
  text "5" at 6182.5,7217.5 h60
  text "Layer 2 - GND" at 6592.41,7217.5 h60
  text "Copper" at 8012,7217.5 h60
  text "1.20mil" at 8931.75,7217.5 h60
  text "6" at 6182.5,7097.5 h60
  text "Dielectric 2" at 6592.41,7097.5 h60
  text "370H (1-2116)" at 8012,7097.5 h60
  text "4.10mil" at 8931.75,7097.5 h60
  text "4.2" at 9581.58,7097.5 h60
  text "7" at 6182.5,6977.5 h60
  text "Layer 3 - Signal / PWR" at 6592.41,6977.5 h60
  text "Copper" at 8012,6977.5 h60
  text "0.60mil" at 8931.75,6977.5 h60
  text "8" at 6182.5,6857.5 h60
  text "Dielectric 3" at 6592.41,6857.5 h60
  text "370H (1080)" at 8012,6857.5 h60
  text "5.70mil" at 8931.75,6857.5 h60
  text "4.2" at 9581.58,6857.5 h60
  text "9" at 6182.5,6737.5 h60
  text "Dielectric 4" at 6592.41,6737.5 h60
  text "370H (4-7628)" at 8012,6737.5 h60
  text "28.00mil" at 8931.75,6737.5 h60
  text "4.2" at 9581.58,6737.5 h60
  text "10" at 6182.5,6617.5 h60
  text "Dielectric 5" at 6592.41,6617.5 h60
  text "370H (1080)" at 8012,6617.5 h60
  text "5.70mil" at 8931.75,6617.5 h60
  text "4.2" at 9581.58,6617.5 h60
  text "11" at 6182.5,6497.5 h60
  text "Layer 4 - Signal / PWR" at 6592.41,6497.5 h60
  text "Copper" at 8012,6497.5 h60
  text "0.60mil" at 8931.75,6497.5 h60
  text "12" at 6182.5,6377.5 h60
  text "Dielectric 6" at 6592.41,6377.5 h60
  text "370H (1-2116)" at 8012,6377.5 h60
  text "4.10mil" at 8931.75,6377.5 h60
  text "4.2" at 9581.58,6377.5 h60
  text "13" at 6182.5,6257.5 h60
  text "Layer 5 - PWR" at 6592.41,6257.5 h60
  text "Copper" at 8012,6257.5 h60
  text "1.20mil" at 8931.75,6257.5 h60
  text "14" at 6182.5,6137.5 h60
  text "Dielectric 7" at 6592.41,6137.5 h60
  text "370H (1080HRC)" at 8012,6137.5 h60
  text "3.40mil" at 8931.75,6137.5 h60
  text "4.2" at 9581.58,6137.5 h60
  text "15" at 6182.5,6017.5 h60
  text "Layer 6 - Bottom Layer" at 6592.41,6017.5 h60
  text "Copper" at 8012,6017.5 h60
  text "1.20mil" at 8931.75,6017.5 h60
  text "16" at 6182.5,5897.5 h60
  text "Bottom Solder" at 6592.41,5897.5 h60
  text "Solder Resist" at 8012,5897.5 h60
  text "0.50mil" at 8931.75,5897.5 h60
  text "3.5" at 9581.58,5897.5 h60
  text "17" at 6182.5,5777.5 h60
  text "Bottom Overlay" at 6592.41,5777.5 h60
  text ".Layer_Name" at 577,-858.49 h60
M13 Component Bodies Top:
  text ".Layer_Name" at 577,-858.49 h60
M14 Component Bodies Bottom:
  text ".Layer_Name" at 577,-858.49 h60
M15 Courtyards Top:
  text ".Layer_Name" at 577,-858.49 h60
M16 Courtyards Bottom:
  text ".Layer_Name" at 577,-858.49 h60
Drill Drawing:
  drawing of 169 lines, arcs and shapes, not listed
  text "Symbol" at 7365.77,2585.59 h72
  text "Quantity" at 7651.52,2585.59 h72
  text "Finished Hole Size" at 7968.7,2585.59 h72
  text "Plated" at 8590.45,2585.59 h72
  text "Hole Type" at 8834.77,2585.59 h72
  text "Drill Layer Pair" at 9195.11,2585.59 h72
  text "Hole Length" at 10373.26,2585.59 h72
  text "2" at 7651.52,2485.96 h60
  text "40.16mil (1.020mm)" at 7968.7,2485.96 h60
  text "NPTH" at 8590.45,2485.96 h60
  text "Round" at 8834.77,2485.96 h60
  text "Layer 1 - Top Layer - Layer 6 - Bottom Layer" at 9195.11,2485.96 h60
  text "-" at 10373.26,2485.96 h60
  text "2" at 7651.52,2386.34 h60
  text "62.99mil (1.600mm)" at 7968.7,2386.34 h60
  text "NPTH" at 8590.45,2386.34 h60
  text "Round" at 8834.77,2386.34 h60
  text "Layer 1 - Top Layer - Layer 6 - Bottom Layer" at 9195.11,2386.34 h60
  text "-" at 10373.26,2386.34 h60
  text "2" at 7651.52,2286.72 h60
  text "86.61mil (2.200mm)" at 7968.7,2286.72 h60
  text "NPTH" at 8590.45,2286.72 h60
  text "Round" at 8834.77,2286.72 h60
  text "Layer 1 - Top Layer - Layer 6 - Bottom Layer" at 9195.11,2286.72 h60
  text "-" at 10373.26,2286.72 h60
  text "2" at 7651.52,2187.1 h60
  text "127.95mil (3.250mm)" at 7968.7,2187.1 h60
  text "NPTH" at 8590.45,2187.1 h60
  text "Round" at 8834.77,2187.1 h60
  text "Layer 1 - Top Layer - Layer 6 - Bottom Layer" at 9195.11,2187.1 h60
  text "-" at 10373.26,2187.1 h60
  text "46" at 7651.52,2087.47 h60
  text "7.87mil (0.200mm)" at 7968.7,2087.47 h60
  text "PTH" at 8590.45,2087.47 h60
  text "Round" at 8834.77,2087.47 h60
  text "Layer 1 - Top Layer - Layer 6 - Bottom Layer" at 9195.11,2087.47 h60
  text "-" at 10373.26,2087.47 h60
  text "B" at 7344.14,2077.48 h44.28
  text "203" at 7651.52,1987.85 h60
  text "7.99mil (0.203mm)" at 7968.7,1987.85 h60
  text "PTH" at 8590.45,1987.85 h60
  text "Round" at 8834.77,1987.85 h60
  text "Layer 1 - Top Layer - Layer 6 - Bottom Layer" at 9195.11,1987.85 h60
  text "-" at 10373.26,1987.85 h60
  text "D" at 7344.14,1977.86 h44.28
  text "177" at 7651.52,1888.23 h60
  text "8.00mil (0.203mm)" at 7968.7,1888.23 h60
  text "PTH" at 8590.45,1888.23 h60
  text "Round" at 8834.77,1888.23 h60
  text "Layer 1 - Top Layer - Layer 6 - Bottom Layer" at 9195.11,1888.23 h60
  text "-" at 10373.26,1888.23 h60
  text "G" at 7344.14,1878.24 h44.28
  text "298" at 7651.52,1788.61 h60
  text "9.99mil (0.254mm)" at 7968.7,1788.61 h60
  text "PTH" at 8590.45,1788.61 h60
  text "Round" at 8834.77,1788.61 h60
  text "Layer 1 - Top Layer - Layer 6 - Bottom Layer" at 9195.11,1788.61 h60
  text "-" at 10373.26,1788.61 h60
  text "F" at 7344.14,1778.61 h44.28
  text "1146" at 7651.52,1688.98 h60
  text "10.00mil (0.254mm)" at 7968.7,1688.98 h60
  text "PTH" at 8590.45,1688.98 h60
  text "Round" at 8834.77,1688.98 h60
  text "Layer 1 - Top Layer - Layer 6 - Bottom Layer" at 9195.11,1688.98 h60
  text "-" at 10373.26,1688.98 h60
  text "E" at 7344.14,1678.99 h44.28
  text "8" at 7651.52,1589.36 h60
  text "35.43mil (0.900mm)" at 7968.7,1589.36 h60
  text "PTH" at 8590.45,1589.36 h60
  text "Round" at 8834.77,1589.36 h60
  text "Layer 1 - Top Layer - Layer 6 - Bottom Layer" at 9195.11,1589.36 h60
  text "-" at 10373.26,1589.36 h60
  text "2" at 7651.52,1489.74 h60
  text "39.37mil (1.000mm)" at 7968.7,1489.74 h60
  text "PTH" at 8590.45,1489.74 h60
  text "Round" at 8834.77,1489.74 h60
  text "Layer 1 - Top Layer - Layer 6 - Bottom Layer" at 9195.11,1489.74 h60
  text "-" at 10373.26,1489.74 h60
  text "9" at 7651.52,1390.12 h60
  text "42.91mil (1.090mm)" at 7968.7,1390.12 h60
  text "PTH" at 8590.45,1390.12 h60
  text "Round" at 8834.77,1390.12 h60
  text "Layer 1 - Top Layer - Layer 6 - Bottom Layer" at 9195.11,1390.12 h60
  text "-" at 10373.26,1390.12 h60
  text "2" at 7651.52,1290.5 h60
  text "51.18mil (1.300mm)" at 7968.7,1290.5 h60
  text "PTH" at 8590.45,1290.5 h60
  text "Round" at 8834.77,1290.5 h60
  text "Layer 1 - Top Layer - Layer 6 - Bottom Layer" at 9195.11,1290.5 h60
  text "-" at 10373.26,1290.5 h60
  text "2" at 7651.52,1190.87 h60
  text "62.99mil (1.600mm)" at 7968.7,1190.87 h60
  text "PTH" at 8590.45,1190.87 h60
  text "Round" at 8834.77,1190.87 h60
  text "Layer 1 - Top Layer - Layer 6 - Bottom Layer" at 9195.11,1190.87 h60
  text "-" at 10373.26,1190.87 h60
  text "2" at 7651.52,1091.25 h60
  text "125.20mil (3.180mm)" at 7968.7,1091.25 h60
  text "PTH" at 8590.45,1091.25 h60
  text "Round" at 8834.77,1091.25 h60
  text "Layer 1 - Top Layer - Layer 6 - Bottom Layer" at 9195.11,1091.25 h60
  text "-" at 10373.26,1091.25 h60
  text "A" at 7344.14,1081.26 h44.28
  text "4" at 7651.52,991.63 h60
  text "125.98mil (3.200mm)" at 7968.7,991.63 h60
  text "PTH" at 8590.45,991.63 h60
  text "Round" at 8834.77,991.63 h60
  text "Layer 1 - Top Layer - Layer 6 - Bottom Layer" at 9195.11,991.63 h60
  text "-" at 10373.26,991.63 h60
  text "2" at 7651.52,892.01 h60
  text "39.37mil (1.000mm)" at 7968.7,892.01 h60
  text "PTH" at 8590.45,892.01 h60
  text "Slot" at 8834.77,892.01 h60
  text "Layer 1 - Top Layer - Layer 6 - Bottom Layer" at 9195.11,892.01 h60
  text "69.88mil (1.775mm)" at 10373.26,892.01 h60
  text "2" at 7651.52,792.38 h60
  text "39.37mil (1.000mm)" at 7968.7,792.38 h60
  text "PTH" at 8590.45,792.38 h60
  text "Slot" at 8834.77,792.38 h60
  text "Layer 1 - Top Layer - Layer 6 - Bottom Layer" at 9195.11,792.38 h60
  text "74.41mil (1.890mm)" at 10373.26,792.38 h60
  text "2" at 7651.52,692.76 h60
  text "39.37mil (1.000mm)" at 7968.7,692.76 h60
  text "PTH" at 8590.45,692.76 h60
  text "Slot" at 8834.77,692.76 h60
  text "Layer 1 - Top Layer - Layer 6 - Bottom Layer" at 9195.11,692.76 h60
  text "78.74mil (2.000mm)" at 10373.26,692.76 h60
  text "1913 Total" at 7651.52,593.14 h60
  text "Slot definitions :" at 7365.77,513.52 h60
  text "Routed Path Length" at 7809.08,513.52 h60
  text "= Calculated from tool start centre position to tool end centre position." at 8341.41,513.52 h60
  text "Hole Length" at 7809.08,463.8 h60
  text "= Routed Path Length + Tool Size = Slot length as defined in the PCB layout" at 8141.61,463.8 h60
  text ".Layer_Name" at 577,-858.49 h60
M17 Embedded Cavity:
  text ".Layer_Name" at 577,-858.49 h60
M18 Embedded Assembly:
  text ".Layer_Name" at 577,-858.49 h60
M19 Embedded Keepout:
  text ".Layer_Name" at 577,-858.49 h60

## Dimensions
0,-400 to 1000,-400 on M2 Board Dimensions
0,0 to 7000,0 on M2 Board Dimensions
0,0 to 0,3600 on M2 Board Dimensions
